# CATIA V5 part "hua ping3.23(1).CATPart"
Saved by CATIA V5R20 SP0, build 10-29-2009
Part number: 花瓶3.23
Material "Bathroom Floor": density 2770 kg/m3, Young's modulus 6e+10 Pa, Poisson ratio 0.3
Material "Wall of Bricks": density 1900 kg/m3
Material "Grey Blue": density 7860 kg/m3, Young's modulus 2e+11 Pa, Poisson ratio 0.266
Bounding box of the stored display mesh (mm): x -35.179 to 30, y -30.758 to 29.969, z -0.9 to 127.946
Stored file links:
  D:\QQ\2382019442\FileRecv\hua ping3.23(1).CATPart
  D:\CATIA V5 R20 WIN64\CATIA V5 R20\win_b64\startup\materials\Catalog.CATMaterial
  D:\CATIA V5 R20 WIN64\CATIA V5 R20\win_b64\startup\materials\yellow_env_512x512.jpg
  D:\CATIA V5 R20 WIN64\CATIA V5 R20\win_b64\startup\materials\wall_of_bricks.jpg
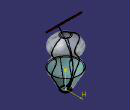
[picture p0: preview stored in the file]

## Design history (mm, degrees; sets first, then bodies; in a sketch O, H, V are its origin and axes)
Body1 (main body), material "Grey Blue"
  Plane1: type Offset, RefPlane xy-plane, Offset 20
  Plane2: type Offset, RefPlane Plane1, Offset 20
  Plane3: type Offset, RefPlane Plane2, Offset 20
  Plane4: type Offset, RefPlane Plane3, Offset 20
  Plane5: type Offset, RefPlane Plane4, Offset 20
  Sketch1 on Plane5, origin (0, 0, 100), H (1, 0, 0), V (0, 1, 0)
    circle A1 centre (0, 0) radius 10
  Sketch2 on Plane4, origin (0, 0, 80), H (1, 0, 0), V (0, 1, 0)
    circle A1 centre (0, 0) radius 30
    point P1 (30, 0)
    coincidence: A1 P1, P1 H
  Sketch3 on Plane3, origin (0, 0, 60), H (1, 0, 0), V (0, 1, 0)
    circle A1 centre (0, 0) radius 20
  Sketch4 on Plane2, origin (0, 0, 40), H (1, 0, 0), V (0, 1, 0)
    circle A1 centre (0, 0) radius 30
  Sketch5 on Plane1, origin (0, 0, 20), H (1, 0, 0), V (0, 1, 0)
    circle A1 centre (0, 0) radius 20
  Sketch6 on xy-plane, origin (0, 0, 0), H (1, 0, 0), V (0, 1, 0)
    circle A1 centre (0, 0) radius 10
    point P1 (10, 0)
    coincidence: A1 P1, P1 H
  Loft1: solid, Sections (Sketch1; Sketch2; Sketch3; Sketch4; Sketch5; Sketch6)
  Sketch7 on yz-plane, origin (0, 0, 0), H (0, 1, 0), V (0, 0, 1)
    axis line L1 (0, 108.9091) -> (0, -10.8162)
    point P1 (0, 108.9091)
    coincidence: P1 V
    vertical: L1 V
  Sketch8 on Plane5, origin (0, 0, 100), H (1, 0, 0), V (0, 1, 0)
    circle A1 centre (0, 0) radius 10
  Sketch9 on Plane4, origin (0, 0, 80), H (1, 0, 0), V (0, 1, 0)
    circle A1 centre (0, 0) radius 30
    point P1 (30, 0)
    coincidence: A1 P1, P1 H
  Sketch10 on Plane3, origin (0, 0, 60), H (1, 0, 0), V (0, 1, 0)
    circle A1 centre (0, 0) radius 20
  Sketch11 on Plane2, origin (0, 0, 40), H (1, 0, 0), V (0, 1, 0)
    circle A1 centre (0, 0) radius 30
  Sketch12 on Plane1, origin (0, 0, 20), H (1, 0, 0), V (0, 1, 0)
    circle A1 centre (0, 0) radius 20
  Sketch13 on xy-plane, origin (0, 0, 0), H (1, 0, 0), V (0, 1, 0)
    circle A1 centre (0, 0) radius 10
    point P1 (10, 0)
    coincidence: A1 P1, P1 H
  Loft2: solid, Sections (Sketch8; Sketch9; Sketch10; Sketch11; Sketch12; Sketch13)
  Shell1: IntOffset 1, Face face of Loft2, ExtOffset 0
Body2, material "Bathroom Floor"
  Sketch14 on yz-plane, origin (0, 0, 0), H (0, 1, 0), V (0, 0, 1)
    axis line L1 (0, 110.3691) -> (0, -19.2116)
    point P1 (0, 110.3691)
    point P3 (0, 40.6511)
    line L2 (0, 40.6511) -> (-29.8466, 40.6511)
    line L3 (-29.8466, 40.6511) -> (-7.8535, 0)
    point P5 (-7.8535, 0)
    line L4 (-7.8535, 0) -> (0, 0)
    coincidence: P1 V, P3 L1, P5 H
    vertical: L1 V
    horizontal: L2 H, L4 H
  Shaft1: profile Sketch14, axis Sketch14.L1, angle 360
  Shell2: IntOffset 1, ExtOffset 0
Body3, material "Wall of Bricks"
  Sketch15 on yz-plane, origin (0, 0, 0), H (0, 1, 0), V (0, 0, 1)
    spline S1 through (-4.1125, 0) (13.3998, 33.6457) (-15.7874, 107.951)
    point P1 (-4.1125, 0)
    coincidence: P1 H
  Plane6: type Normal, Curve Sketch15, RefPoint vertex of Sketch15
  Sketch16 on Plane6, origin (0, -61.5501, 63.807), H (1, 0, 0), V (0, 0.7197, 0.6943)
    circle A1 centre (0, 64.4884) radius 0.5
    point P1 (0, 64.4884)
    radius A1 = 0.5
    coincidence: P1 V
  Rib1: profile Sketch16, centre curve Sketch15
  Sketch17 on Plane6, origin (0, -61.5501, 63.807), H (1, 0, 0), V (0, 0.7197, 0.6943)
    spline S1 through (-4.7218, 57.9871) (13.9314, 62.3213) (19.8382, 57.9871) (24.1907, 72.8472) (-4.7218, 87.3976) (-30.8363, 90.1839) (-23.9968, 53.9625) (-9.0742, 44.9846) (-4.7218, 57.9871)
    point P1 (-4.7218, 57.9871)
    point P2 (-4.7218, 57.9871)
    coincidence: P1 P2
  Pad1: profile Sketch17, direction (0, -0.6943, 0.7197), length 2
